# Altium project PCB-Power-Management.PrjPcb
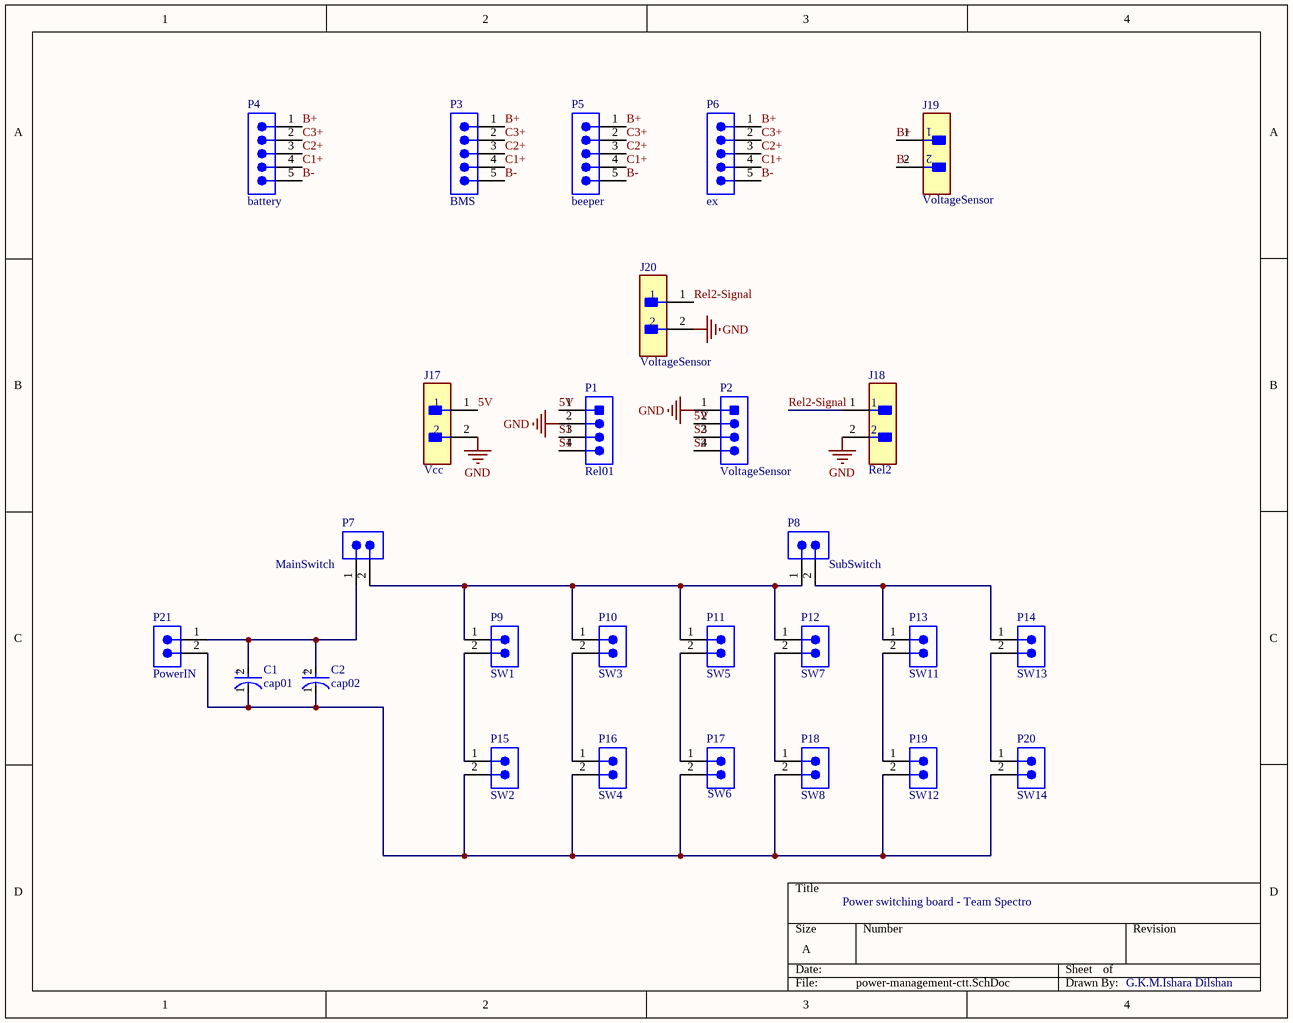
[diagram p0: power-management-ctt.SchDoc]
2 sheets, 44 parts. Net scope: global (net labels, ports and power ports of the same name join across sheets).
Board files: PCB-Power-Managemet-pcb.PcbDoc, PCB2-dockstation.PcbDoc
Sheets:
  power-management-ctt.SchDoc
  dockstation.SchDoc

## Sheet power-management-ctt.SchDoc
size A; SheetNumber: 1; SheetTotal: 2

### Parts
C1  cap01  [FP-RAD-TH-D_16_0_5-L_25_2-MFG]
C2  cap02  [FP-RAD-TH-D_16_0_5-L_25_2-MFG]
J17  Vcc  [FP-M20-9990245-MFG]
J18  Rel2  [FP-M20-9990245-MFG]
J19  VoltageSensor  [FP-M20-9990245-MFG]
J20  VoltageSensor  [FP-M20-9990245-MFG]
P1  Rel01  [MOLX-22-27-2041_V]
P2  VoltageSensor  [MOLX-22-27-2041_V]
P3  BMS  [691311500105]
P4  battery  [691311500105]
P5  beeper  [691311500105]
P6  ex  [691311500105]
P7  MainSwitch  [691313410002]
P8  SubSwitch  [691313410002]
P9  SW1  [691313410002]
P10  SW3  [691313410002]
P11  SW5  [691313410002]
P12  SW7  [691313410002]
P13  SW11  [691313410002]
P14  SW13  [691313410002]
P15  SW2  [691313410002]
P16  SW4  [691313410002]
P17  SW6  [691313410002]
P18  SW8  [691313410002]
P19  SW12  [691313410002]
P20  SW14  [691313410002]
P21  PowerIN  [691313410002]

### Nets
GND: J17.2 J18.2 J20.2 P1.2 P2.1
5V: J17.1 P1.1 P2.2
B+: J19.1 P3.1 P4.1 P5.1 P6.1
B-: J19.2 P3.5 P4.5 P5.5 P6.5
C1+: P3.4 P4.4 P5.4 P6.4
C2+: P3.3 P4.3 P5.3 P6.3
C3+: P3.2 P4.2 P5.2 P6.2
Rel2-Signal: J18.1 J20.1
S1: P1.3 P1.4
S2: P2.3 P2.4
NetC1_1: C1.1(C) C2.1(C) P15.2 P16.2 P17.2 P18.2 P19.2 P20.2 P21.2
NetC1_2: C1.2(A) C2.2(A) P7.1 P21.1
NetP7_2: P7.2 P8.1 P9.1 P10.1 P11.1 P12.1
NetP8_2: P8.2 P13.1 P14.1
NetP9_2: P9.2 P15.1
NetP10_2: P10.2 P16.1
NetP11_2: P11.2 P17.1
NetP12_2: P12.2 P18.1
NetP13_2: P13.2 P19.1
NetP14_2: P14.2 P20.1

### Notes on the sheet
- Power switching board - Team Spectro
- G.K.M.Ishara Dilshan

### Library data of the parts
C1 C2 = CMP-05427-000445-1: Aluminum Electrolytic Capacitors (Radial Lead Type) 4700uF ±20% 16V; Impedance: 14mR; Ripple Current (AC): 3.82A; Life (Hours): 10000Hour; Lead/Base Style: Straight; Capacitance: 4.7mF; Lead Diameter: 0.8mm
J17-J20 = CMP-15831-000105-1: CONN HEADER VERT 2POS 2.54MM; Working Voltage: 750V; Gender: Male; Number of Poles: 2; Current Rating: 3A; Mated Stacking Heights: 16.54mm; Contact Resistance: 25mR; Connector Type: Male Pin; Insulation Resistance: 10GR; Mating Cycles: 300; Voltage: 50V
P1 P2 = CMP-2000-05243-1: Male Header, Pitch 2.54 mm, 1 x 4 Position, Height 11.7 mm, Tail Length 3.56 mm, RoHS, Bulk; Manufacturer: Molex; Voltage rating: 250V; Current rating: 4A
P3-P6 = CMP-1502-02149-2: NexarPartId: 8917750; Pitch: 5.08mm; Voltage: 300V; Number of Positions Per Level: 5; Number of Levels: 1; Gender: Male; Current: 20A
P7-P21 = CMP-1502-02424-2: NexarPartId: 18818328; Gender: Male; Pitch: 7.62mm; Current: 20A; Connector Type: PCB, Terminal Block; Voltage: 300V; Number of Positions Per Level: 2; Number of Levels: 1

## Sheet dockstation.SchDoc
size A; SheetNumber: 2; SheetTotal: 2
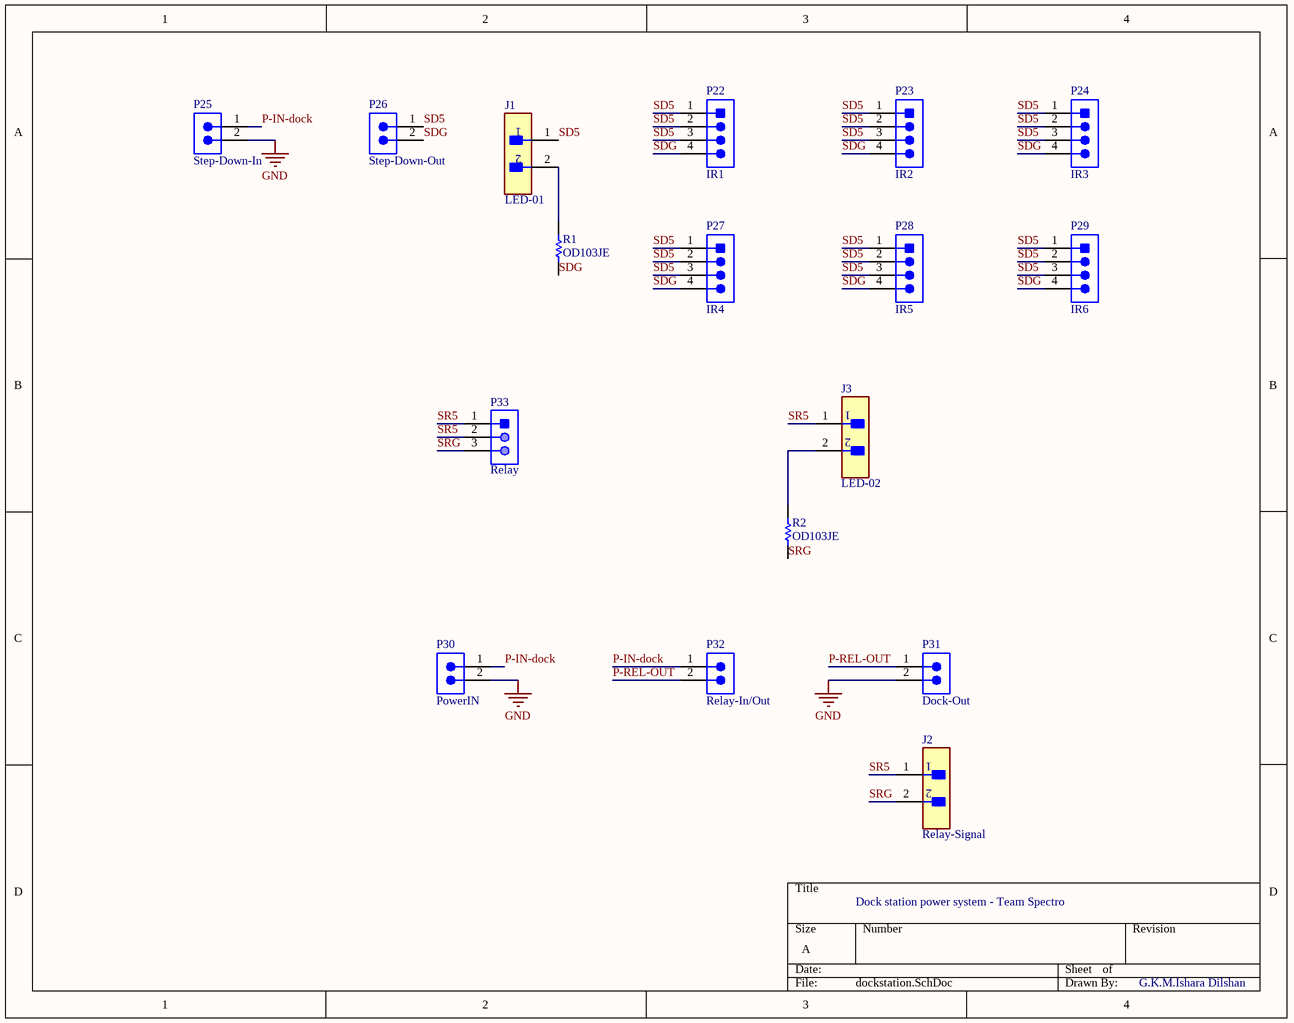
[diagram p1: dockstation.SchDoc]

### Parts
J1  LED-01  [FP-M20-9990245-MFG]
J2  Relay-Signal  [FP-M20-9990245-MFG]
J3  LED-02  [FP-M20-9990245-MFG]
P22  IR1  [MOLX-22-27-2041_V]
P23  IR2  [MOLX-22-27-2041_V]
P24  IR3  [MOLX-22-27-2041_V]
P25  Step-Down-In  [691313410002]
P26  Step-Down-Out  [691313410002]
P27  IR4  [MOLX-22-27-2041_V]
P28  IR5  [MOLX-22-27-2041_V]
P29  IR6  [MOLX-22-27-2041_V]
P30  PowerIN  [691313410002]
P31  Dock-Out  [691313410002]
P32  Relay-In/Out  [691313410002]
P33  Relay  [JST-B3B-PH-K-S-3_V]
R1  OD103JE  [OMTE-RES7X2.5-2]
R2  OD103JE  [OMTE-RES7X2.5-2]

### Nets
GND: P25.2 P30.2 P31.2
P-IN-dock: P25.1 P30.1 P32.1
P-REL-OUT: P31.1 P32.2
SD5: J1.1 P22.1 P22.2 P22.3 P23.1 P23.2 P23.3 P24.1 P24.2 P24.3 P26.1 P27.1 P27.2 P27.3 P28.1 P28.2 P28.3 P29.1 P29.2 P29.3
SDG: P22.4 P23.4 P24.4 P26.2 P27.4 P28.4 P29.4 R1.1
SR5: J2.1 J3.1 P33.1 P33.2
SRG: J2.2 P33.3 R2.2
NetJ1_2: J1.2 R1.2
NetJ3_2: J3.2 R2.1

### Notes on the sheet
- Dock station power system - Team Spectro
- G.K.M.Ishara Dilshan

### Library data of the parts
J1-J3 = CMP-15831-000105-1: as J17 on sheet power-management-ctt
P22-P24 P27-P29 = CMP-2000-05243-1: as P1 on sheet power-management-ctt
P25 P26 P30-P32 = CMP-1502-02424-2: as P7 on sheet power-management-ctt
P33 = CMP-2000-05164-1: Male Header, Pitch 2 mm, 1 x 3 Position, Height 6 mm, Tail Length 3.4 mm, -25 to 85 degC, RoHS, Bulk; Manufacturer: JST; Style/Orientation: StraightHeader/Plug; Pitch: 2mm; No of Positions: 3
R1 R2 = CMP-2000-06865-1: Little Demon(R) Carbon Composition Molded OD Series, 250 V, 10 KOhm, +/-5%, -70 to 130 degC, 2-Pin THD, RoHS, Bulk; Manufacturer: Ohmite; Resistance (Ohms): 10k; Power Rating: 0.25W; Power (Watts): 0.25W,1/4W; Tolerance: ±5%; Online Catalog: OD,OF,OASeries,LittleDemon®; Catalog Drawings: OD,OF,OASeries; EDA / CAD Models: DownloadfromAcceleratedDesigns

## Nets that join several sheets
GND: power-management-ctt (5 pins), dockstation (P25.2 P30.2 P31.2)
